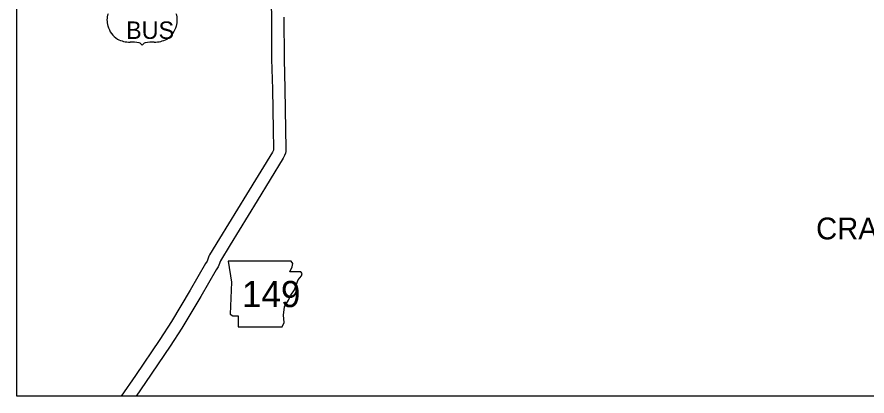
# Model space of a CAD drawing. Extents: x -117616 to 64730, y 54117 to 789866.
# Drawn here: x 61556.6 to 61762, y 55371.1 to 55462.7 of the extents above; entities that cross this region are included whole.
import ezdxf

# ---------------------------------------------------------------- set-up
doc = ezdxf.new("R2010")
doc.units = 0
for name, color, linetype in [('10', 7, 'Continuous'), ('21', 7, 'Continuous'), ('22', 7, 'Continuous'), ('6', 7, 'Continuous'), ('R_No Plot', 7, 'Continuous')]:
    doc.layers.add(name, color=color, linetype=linetype)

msp = doc.modelspace()

# ---------------------------------------------------------------- linework, layer by layer
at = {"layer": '10'}
for points in [[(61608.18, 55495.1), (61608.34, 55490.09), (61617.46, 55490.33), (61617.72, 55478.27), (61618.05, 55462.63)], [(61618.05, 55462.65), (61618.11, 55452.47), (61618.32, 55445.24), (61618.47, 55435.44), (61618.58, 55430.87), (61618.57, 55430.54), (61618.53, 55430.45), (61618.3, 55430), (61612.06, 55419.77), (61605.5, 55409.14), (61603.09, 55405.18), (61602.93, 55404.85), (61602.8, 55404.41), (61602.7, 55404.1), (61602.52, 55403.66), (61602.16, 55403.05), (61598.41, 55396.63), (61593.89, 55389.06), (61591.11, 55384.75), (61585.18, 55376.04), (61581.78, 55371.05)], [(61621.05, 55462.67), (61621.11, 55452.52), (61621.31, 55445.31), (61621.47, 55435.49), (61621.58, 55430.87), (61621.56, 55430.14), (61621.48, 55429.75), (61621.26, 55429.2), (61620.91, 55428.53), (61614.62, 55418.2), (61608.06, 55407.58), (61605.72, 55403.72), (61605.67, 55403.54), (61605.52, 55403.07), (61605.21, 55402.32), (61604.74, 55401.53), (61600.99, 55395.1), (61596.44, 55387.48), (61593.61, 55383.09), (61587.66, 55374.35), (61585.41, 55371.05)]]:
    msp.add_lwpolyline(points, dxfattribs=at)
at = {"layer": '21'}
msp.add_lwpolyline([(61607.64, 55403.65), (61608.4, 55398.57), (61608.06, 55390.87), (61608.74, 55390.45), (61610.01, 55390.45), (61610.01, 55387.75), (61620.67, 55387.75), (61621.18, 55388.84), (61621.01, 55390.62), (61621.26, 55392.65), (61622.19, 55394.26), (61622.78, 55395.44), (61623.63, 55396.71), (61624.14, 55398.07), (61624.56, 55399.16), (61625.32, 55400.1), (61625.49, 55400.69), (61625.15, 55401.11), (61622.53, 55401.11), (61623.12, 55402.29), (61623.21, 55403.06), (61622.86, 55403.64)], close=True, dxfattribs=at)
at = {"layer": '22'}
for centre, radius, start, end in [((61583.07, 55461.92), 4.75, 160.9576, 197.3819), ((61590.57, 55461.92), 4.75, 342.6181, 19.0424), ((61583.85, 55461.94), 5.5, 195.1074, 237.1312), ((61589.8, 55461.94), 5.5, 302.8688, 344.8926), ((61583.95, 55463.67), 7.06, 244.0771, 269.5779), ((61584.11, 55443.68), 12.93, 81.1942, 90.9539), ((61585.73, 55455.27), 1.24, 28.0342, 72.9864), ((61587.92, 55455.27), 1.24, 107.0136, 151.9658), ((61589.53, 55443.68), 12.93, 89.0461, 98.8058), ((61589.7, 55463.67), 7.06, 270.4221, 295.9229)]:
    msp.add_arc(centre, radius, start, end, dxfattribs=at)
at = {"layer": 'R_No Plot'}
msp.add_lwpolyline([(61556.57, 56155.54), (62285.97, 56155.54), (62285.97, 55371.05), (61556.57, 55371.05)], close=True, dxfattribs=at)

# ---------------------------------------------------------------- texts
at = {"layer": '21'}
msp.add_text('149', height=6.336, dxfattribs=at).set_placement((61610.94, 55392.54))
at = {"layer": '22'}
msp.add_text('BUS', height=4.224, dxfattribs=at).set_placement((61582.94, 55457.38))
at = {"layer": '6'}
msp.add_text('CRAWFORDSVILLE', height=5.28, dxfattribs=at).set_placement((61749.71, 55408.91))

doc.saveas('drawing.dxf')
